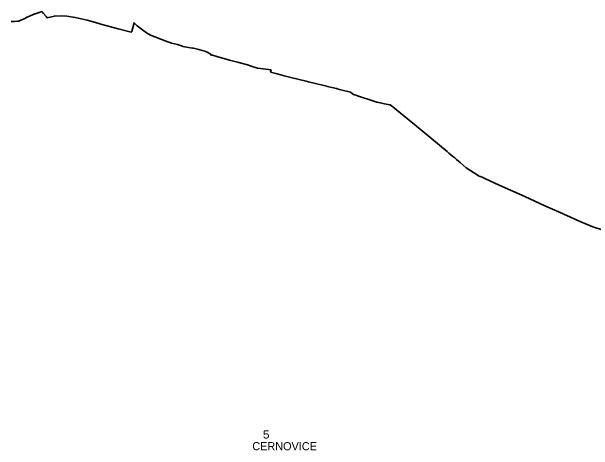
# Model space of a CAD drawing. Extents: x -610940 to -588976, y -1170376 to -1149800.
# Drawn here: x -596255 to -594465, y -1162773 to -1161423 of the extents above; entities that cross this region are included whole.
import ezdxf

# ---------------------------------------------------------------- set-up
doc = ezdxf.new("R2010")
doc.units = 0
doc.header["$LTSCALE"] = 10
doc.layers.add('54', color=7, linetype='Continuous', lineweight=35)
doc.layers.add('55', color=7, linetype='Continuous')
doc.layers.add('56', color=7, linetype='Continuous')

msp = doc.modelspace()

# ---------------------------------------------------------------- linework, layer by layer
at = {"layer": '54'}
for p, q in [((-595556.14, -1161579.65), (-595545.08, -1161582.61)), ((-595545.08, -1161582.61), (-595529.65, -1161586.73)), ((-595520.25, -1161589.57), (-595529.65, -1161586.73))]:
    msp.add_line(p, q, dxfattribs=at)
for points in [[(-596236.34, -1161452.03), (-596233.09, -1161451.73), (-596226.7, -1161448.78), (-596216.78, -1161444.48), (-596207.09, -1161440.18), (-596197.5, -1161435.94), (-596190.62, -1161432.95), (-596183.55, -1161429.84), (-596182.73, -1161429.55), (-596172.84, -1161426.2), (-596162.5, -1161422.66), (-596157.02, -1161428.89), (-596148.75, -1161437.91), (-596145.6, -1161441.3), (-596123.28, -1161436.44), (-596102.25, -1161435.42), (-596085.46, -1161436.91), (-596059.59, -1161440.47), (-596031.41, -1161447.03), (-596022.72, -1161449.41), (-595989.36, -1161458.46), (-595980.08, -1161460.96), (-595927.27, -1161475.59), (-595886.84, -1161486.38), (-595884.75, -1161483.9), (-595878.34, -1161456.92), (-595868.48, -1161466.79), (-595840.49, -1161487.69), (-595827.56, -1161495.29), (-595782.56, -1161512.57), (-595763.23, -1161519.45), (-595744.59, -1161524), (-595729.49, -1161529.36), (-595728.41, -1161529.57), (-595698.54, -1161534.75), (-595694.96, -1161535.37), (-595679.31, -1161539.46), (-595668.99, -1161542.06), (-595660.34, -1161544.24), (-595660.17, -1161544.32)], [(-596256.72, -1161453.27), (-596246.35, -1161452.65), (-596236.34, -1161452.03)], [(-595660.17, -1161544.32), (-595658.75, -1161545.02), (-595655.65, -1161546.55), (-595654.48, -1161547.2), (-595653.42, -1161547.73), (-595648.39, -1161550.37), (-595641.88, -1161553.78), (-595642.13, -1161555.84), (-595638.78, -1161556.64), (-595637.45, -1161557.01), (-595623.49, -1161560.9)], [(-595556.14, -1161579.65), (-595585.08, -1161571.59), (-595623.49, -1161560.9)], [(-595520.25, -1161589.57), (-595517.92, -1161590.27), (-595498.07, -1161596.27), (-595489.3, -1161597.59), (-595456.55, -1161602.34), (-595458.11, -1161608.58), (-595437.58, -1161614.46), (-595416.23, -1161619.95), (-595395.6, -1161625.62), (-595348.83, -1161636.77), (-595341.92, -1161638.41), (-595294.24, -1161649.78), (-595288.42, -1161651.25), (-595287.01, -1161651.61), (-595278.72, -1161653.82), (-595270.31, -1161655.89), (-595264.28, -1161657.38), (-595255.5, -1161659.61), (-595253.05, -1161660.23), (-595245.89, -1161662.06), (-595212.03, -1161670.97), (-595207, -1161674.63), (-595203.05, -1161677.51), (-595195.8, -1161680.21)], [(-595103.18, -1161707.63), (-595107.88, -1161706.63), (-595115.77, -1161704.96), (-595131.64, -1161701.59), (-595143.45, -1161697.65), (-595187.98, -1161682.82), (-595195.8, -1161680.21)], [(-595103.18, -1161707.63), (-595089.97, -1161709.77), (-595082.25, -1161716.13), (-595059.51, -1161734.04), (-595048.2, -1161743.24), (-595015.77, -1161770.05), (-594915.54, -1161853.38), (-594909.55, -1161858.3), (-594897.36, -1161868.33), (-594891.92, -1161872.91), (-594886.16, -1161877.75), (-594880.55, -1161882.49), (-594875.38, -1161886.83), (-594856.69, -1161903.47), (-594817.06, -1161928.69), (-594807.9, -1161932.64), (-594798.75, -1161936.8), (-594755.2, -1161956.62), (-594676.25, -1161992.23), (-594615.06, -1162020.5), (-594567.27, -1162041.09), (-594559.86, -1162044.45), (-594555.74, -1162046.32), (-594503.55, -1162069.48), (-594467.17, -1162084.91), (-594435.67, -1162095.24)]]:
    msp.add_lwpolyline(points, dxfattribs=at)

# ---------------------------------------------------------------- texts
at = {"layer": '55'}
msp.add_text('CERNOVICE ', height=25, dxfattribs=at).set_placement((-595514.56, -1162772.91))
at = {"layer": '56', "width": 1.1}
msp.add_text('5 ', height=25, dxfattribs=at).set_placement((-595482.01, -1162736.82))

doc.saveas('drawing.dxf')
